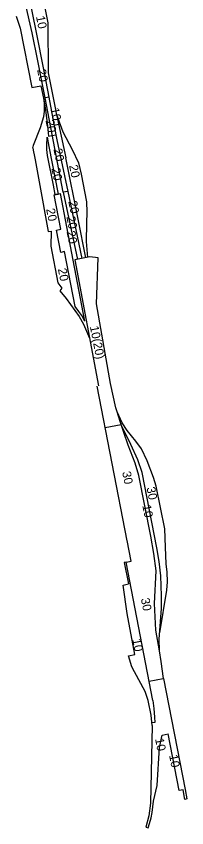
# Model space of a CAD drawing. Extents: x -545967 to -545044, y -1122650 to -1118491.
# Drawn here: x -545489 to -545044, y -1122650 to -1120535 of the extents above; entities that cross this region are included whole.
import ezdxf

# ---------------------------------------------------------------- set-up
doc = ezdxf.new("R2010")
doc.units = 0
doc.layers.add('osvětlené plochy-hodnota-obrys', color=7, linetype='Continuous')

msp = doc.modelspace()

# ---------------------------------------------------------------- linework, layer by layer
at = {"layer": 'osvětlené plochy-hodnota-obrys'}
for p, q in [((-545390.1, -1120818.7), (-545378.5, -1120816.4)), ((-545366.2, -1120993.7), (-545329.4, -1121168.4)), ((-545354.3, -1120991.3), (-545317.4, -1121166.1)), ((-545214.9, -1121599.5), (-545256.6, -1121607.8))]:
    msp.add_line(p, q, dxfattribs=at)
for points in [[(-545425.7, -1120413.6), (-545422.2, -1120472.1), (-545406.8, -1120552), (-545406, -1120682.1)], [(-545413.7, -1120747.5), (-545423.8, -1120695.7), (-545432.7, -1120651.4), (-545447.8, -1120577.9), (-545464.8, -1120502.8), (-545475.5, -1120447.3)], [(-545465.7, -1120446.7), (-545453.9, -1120496.1), (-545438.9, -1120568.4), (-545416.4, -1120682.5), (-545404.2, -1120745.6), (-545418, -1120748.3)], [(-545489.1, -1120534.6), (-545478.7, -1120566), (-545448.6, -1120720.4), (-545424.8, -1120715.8), (-545418, -1120748.3)], [(-545406, -1120682.1), (-545386.9, -1120777.9), (-545383.6, -1120793.2)], [(-545413.7, -1120747.5), (-545418, -1120748.3), (-545416.3, -1120761.3), (-545416.2, -1120781.8), (-545418, -1120797.2), (-545426.8, -1120825.5), (-545444.9, -1120871.4), (-545446, -1120875.4), (-545446.2, -1120876.6), (-545445.9, -1120878.1), (-545444.9, -1120883.8), (-545443.9, -1120888.6), (-545442.5, -1120896.1), (-545439.9, -1120909.4), (-545434.3, -1120937.7), (-545428.9, -1120966.4), (-545405.4, -1121095.4), (-545398.1, -1121095.3), (-545398.5, -1121133.6), (-545380, -1121229.2), (-545370, -1121243.6), (-545375.6, -1121250.3), (-545359, -1121270.5)], [(-545418, -1120748.3), (-545412.9, -1120778.6), (-545407.4, -1120821.6), (-545404.5, -1120847.4), (-545385.3, -1120843.9)], [(-545385.3, -1120843.9), (-545382.8, -1120856.6), (-545354.3, -1120991.3), (-545366.2, -1120993.7), (-545413.7, -1120747.5)], [(-545404.2, -1120745.6), (-545385.3, -1120843.9)], [(-545384, -1120791.3), (-545367.4, -1120835.8), (-545342.7, -1120882), (-545326.5, -1120916.8), (-545319.2, -1120946.5), (-545305.9, -1121018.1), (-545304.5, -1121045.6), (-545305.7, -1121073.9), (-545306.8, -1121121.9), (-545303.4, -1121163.4)], [(-545384, -1120791.3), (-545359.6, -1120903.9)], [(-545379.7, -1120998.3), (-545387.3, -1120999.8), (-545392.1, -1120975.1), (-545392.1, -1120974.7), (-545407.1, -1120897.4), (-545408.8, -1120882.1), (-545409.2, -1120871.2), (-545407.9, -1120850.1), (-545403.6, -1120874.6), (-545379.7, -1120998.4)], [(-545307.7, -1121164.2), (-545327.3, -1121063.8), (-545359.6, -1120903.9)], [(-545309.8, -1121329.7), (-545318.2, -1121314.9), (-545325.5, -1121304.1), (-545335, -1121291.6), (-545363, -1121148.3), (-545373, -1121150.3), (-545384.1, -1121092.3), (-545373, -1121090.1), (-545390.4, -1121000.4), (-545379.7, -1120998.3)], [(-545379.6, -1120998.3), (-545373.8, -1120997.2)], [(-545309.8, -1121329.7), (-545340.4, -1121170.8), (-545373.8, -1120997.2)], [(-545242.6, -1121491.9), (-545279.8, -1121284), (-545274.8, -1121164.4), (-545297, -1121162.2), (-545335.9, -1121169.8), (-545274.2, -1121498.1)], [(-545359, -1121270.5), (-545324.8, -1121317.4), (-545313.1, -1121337.3), (-545297.5, -1121373.7)], [(-545225.6, -1121565.5), (-545228.7, -1121555.5), (-545242.6, -1121491.9)], [(-545199.2, -1121901.5), (-545277.9, -1121498.9)], [(-545114.4, -1122142), (-545095.8, -1122030.8), (-545094, -1122008.5), (-545094.7, -1121983.4), (-545097.7, -1121961.9), (-545099.4, -1121918.6), (-545101.3, -1121870.5), (-545123.7, -1121759.4), (-545130.3, -1121736.6), (-545147.4, -1121693.8), (-545162.4, -1121662.1), (-545176.7, -1121642.6), (-545199.4, -1121614.6), (-545212.2, -1121594), (-545225.6, -1121565.5)], [(-545137.9, -1121889.4), (-545168.6, -1121732), (-545178.3, -1121699.7), (-545197, -1121652.5), (-545208.2, -1121619.3), (-545218, -1121591.1), (-545225.6, -1121565.5)], [(-545115.2, -1122188.8), (-545115.5, -1122158.5), (-545110.1, -1122078.5), (-545109.5, -1122045), (-545111.7, -1121993.5), (-545115.9, -1121955.8), (-545122, -1121920.1), (-545160.5, -1121723.8), (-545171.6, -1121690.9), (-545189.9, -1121650.8), (-545214.9, -1121599.5)], [(-545141.7, -1122267.4), (-545105.6, -1122261.1), (-545104.4, -1122260.6), (-545110.3, -1122216.7), (-545115.2, -1122188.8), (-545124.3, -1122134.3), (-545128.3, -1122065), (-545124.1, -1121980.1), (-545129.6, -1121934.5), (-545137.9, -1121889.4)], [(-545132, -1122317.7), (-545201.8, -1121957.2), (-545188.8, -1121954.7), (-545199.2, -1121901.4)], [(-545201.8, -1121957.2), (-545207.1, -1121958.2), (-545196.2, -1122014.2)], [(-545179.4, -1122198.3), (-545199.6, -1122091.5), (-545209.6, -1122017.2), (-545196.2, -1122014.2)], [(-545186.9, -1122229.9), (-545195.9, -1122201.4), (-545179.4, -1122198.3)], [(-545180.6, -1122243.5), (-545186.9, -1122229.9)], [(-545144.6, -1122318.1), (-545152.1, -1122294.5), (-545180.6, -1122243.5)], [(-545104.4, -1122260.6), (-545048, -1122549.8)], [(-545137.1, -1122356.1), (-545144.6, -1122318.1)], [(-545132, -1122317.7), (-545129.6, -1122339.1), (-545127.9, -1122361.8), (-545127.5, -1122375.2), (-545135.1, -1122376.6)], [(-545134.5, -1122383.1), (-545137.1, -1122356.1)], [(-545134.5, -1122383.1), (-545138.4, -1122585.7), (-545142.7, -1122618.2), (-545150.6, -1122647.8), (-545144.4, -1122649.7)], [(-545136.5, -1122623.9), (-545134.4, -1122610.1), (-545134.4, -1122610.1), (-545130.6, -1122580.5), (-545121.5, -1122539.9), (-545115, -1122440.4), (-545107.7, -1122408.4), (-545092, -1122405.3)], [(-545052.9, -1122550.8), (-545063.3, -1122552.8), (-545092, -1122405.3)], [(-545048.6, -1122575.7), (-545052.9, -1122550.8)], [(-545048, -1122549.8), (-545043.7, -1122574.7), (-545048.6, -1122575.7)], [(-545144.4, -1122649.7), (-545143.7, -1122647.6), (-545136.5, -1122623.9)]]:
    msp.add_lwpolyline(points, dxfattribs=at)

# ---------------------------------------------------------------- texts
for s, p in [('10', (-545437.5, -1120535.8)), ('20', (-545434.6, -1120674.6)), ('10', (-545400, -1120775.3)), ('20', (-545412.7, -1120806.5)), ('20', (-545391.9, -1120881.4)), ('20', (-545351, -1120924.1)), ('20', (-545397.2, -1120931.7)), ('20', (-545353.1, -1121017.8)), ('20', (-545411.1, -1121037.5)), ('20', (-545358.1, -1121057.7)), ('20', (-545357.8, -1121096.2)), ('20', (-545380.4, -1121193.6)), ('10(20)', (-545296.9, -1121343.7)), ('30', (-545212.6, -1121722.9)), ('30', (-545149, -1121763.5)), ('10', (-545160, -1121809.8)), ('30', (-545163.8, -1122053)), ('10', (-545186.2, -1122158.9)), ('10', (-545126.6, -1122418.1)), ('10', (-545090, -1122461))]:
    msp.add_text(s, height=22.78, rotation=281.0956, dxfattribs=at).set_placement(p)

doc.saveas('drawing.dxf')
